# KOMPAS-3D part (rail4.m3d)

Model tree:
1. X Axis
2. Y Axis
3. Z Axis
4. Origin
     Wall Thickness 1 = 1; Wall Thickness 2 = 1; Distance 1 = 50; Distance 2 = 10

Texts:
  Steel DIN 17102
  Three Point Plane
  Plane at Angle
  Line and Point Plane
  Axis through Two Vertices
  Axis of Feature
  Axis of Conical Surface
  Axis through Edge
  Trim by Surface
  Trim by Sketch
  Feature with No History
  Intersection Axis of Two Planes
  Two Line Plane
  Line and Face Plane
  Bend by line
  Hole in sheet body
  Cut in sheet body
  Point in CM
  Linear Dimension from Line to Point
  Surface Finish Symbol
  Geometric Tolerance Symbol
  Leader #1
  Leader #2
  Leader #3
  Shape Deviations and Datum
  Node point number
  Mark of coordination axis
  Node point designation
  Mark/Reference designation with leader
  Mark/reference designation on line
  Mark/Reference designation without leader
  LR4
